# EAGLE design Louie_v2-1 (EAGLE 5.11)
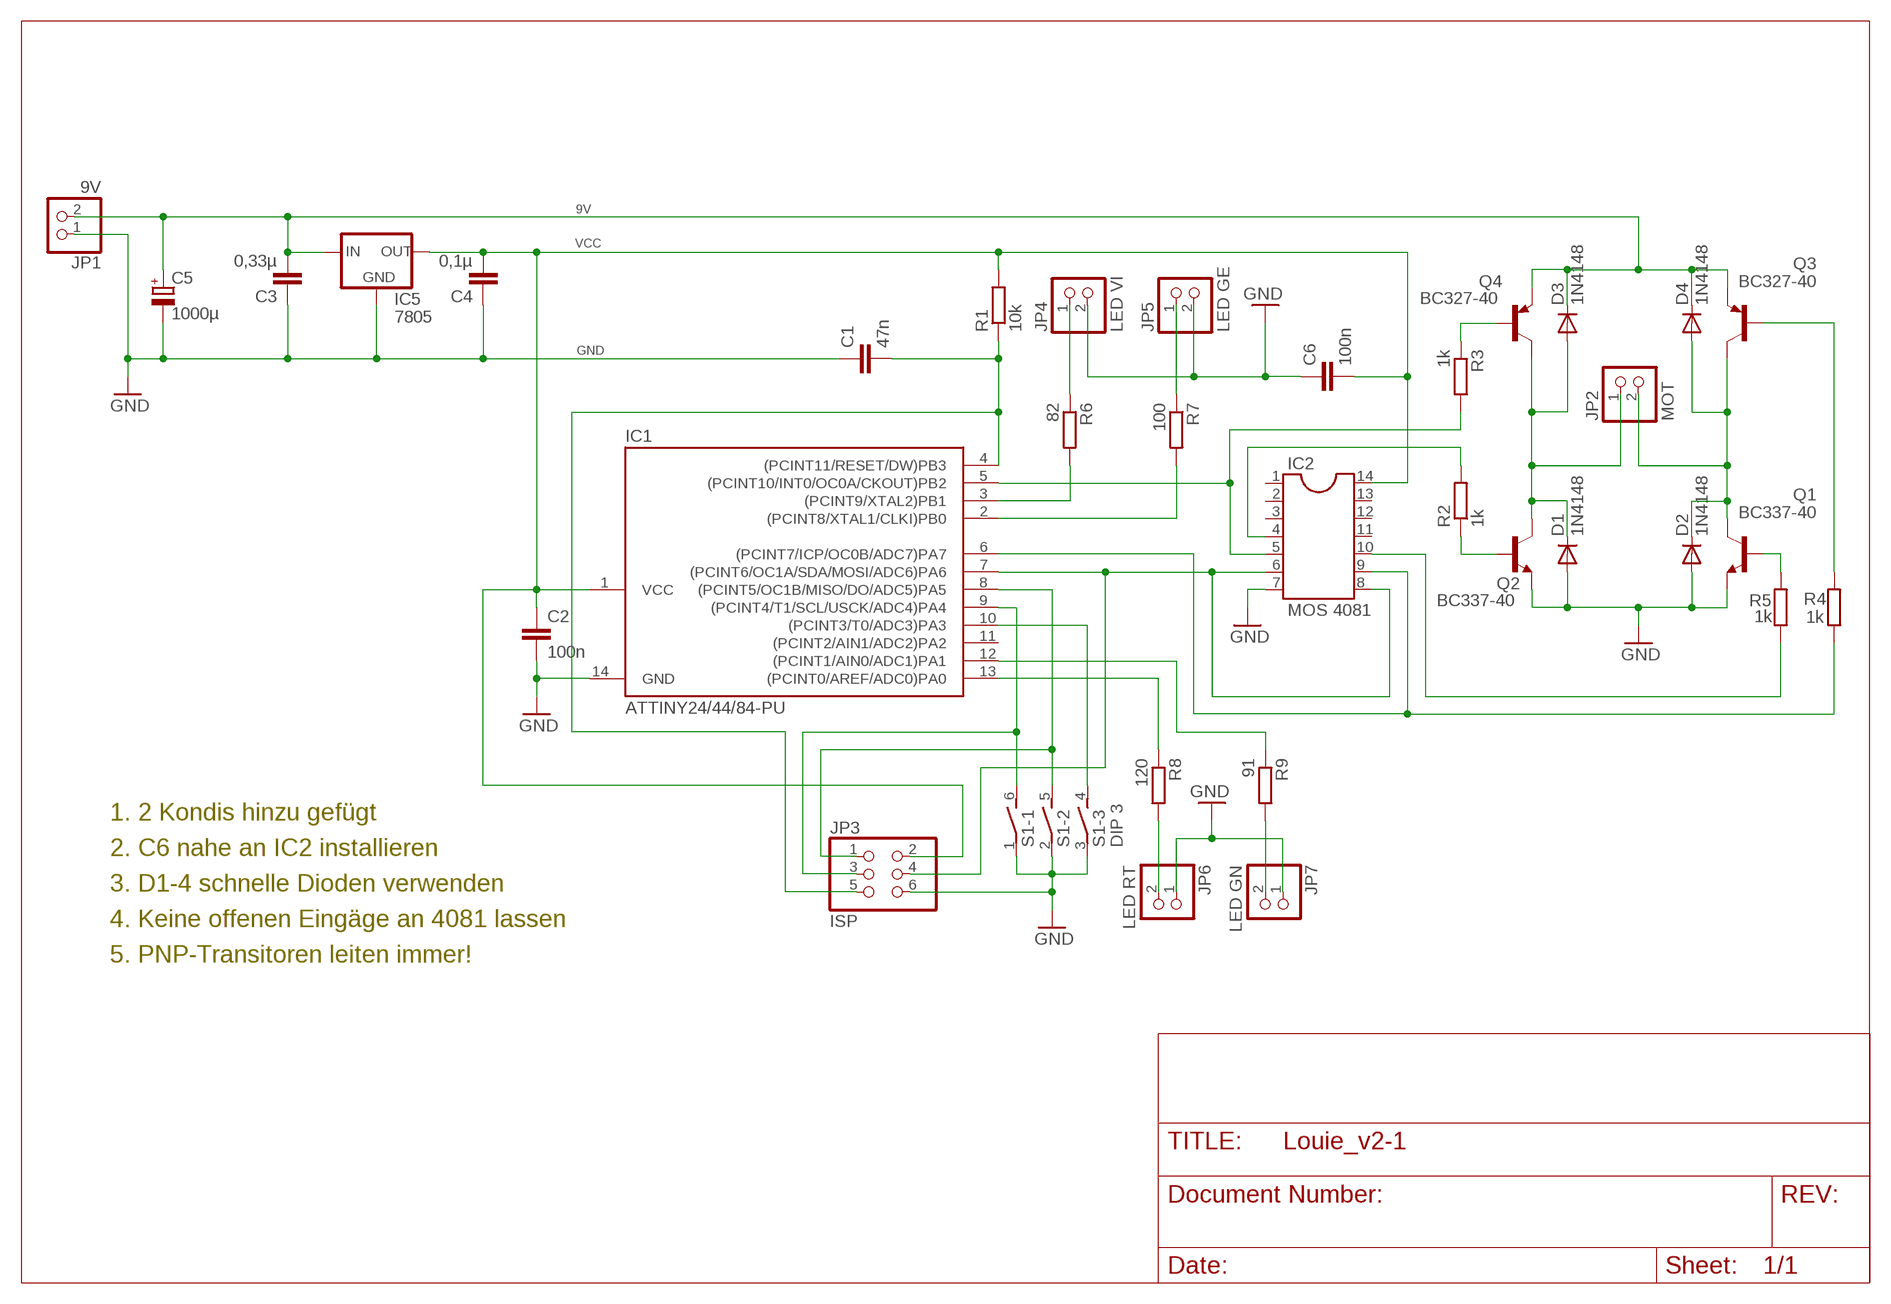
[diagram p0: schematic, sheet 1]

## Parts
C1  47n  C-EU025-025X050  [C025-025X050]
C2  100n  C-EU050-024X044  [C050-024X044]
C3  0,33µ  C-EU025-025X050  [C025-025X050]
C4  0,1µ  C-EU025-025X050  [C025-025X050]
C5  1000µ  CPOL-EUE5-10.5  [E5-10,5]
C6  100n  C-EU050-024X044  [C050-024X044]
D1  1N4148  [DO35-10]
D2  1N4148  [DO35-10]
D3  1N4148  [DO35-10]
D4  1N4148  [DO35-10]
IC1  ATTINY24/44/84-PU  [DIL14]
IC2  MOS 4081  DIL14  [DIL14]
IC5  7805  78XXL  [78XXL]
JP1  9V  PINHD-1X2  [1X02]
JP2  MOT  PINHD-1X2  [1X02]
JP3  ISP  PINHD-2X3  [2X03]
JP4  LED VI  PINHD-1X2  [1X02]
JP5  LED GE  PINHD-1X2  [1X02]
JP6  LED RT  PINHD-1X2  [1X02]
JP7  LED GN  PINHD-1X2  [1X02]
Q1  BC337-40  BC337  [TO92]
Q2  BC337-40  BC337  [TO92]
Q3  BC327-40  BC327  [TO92-EBC]
Q4  BC327-40  BC327  [TO92-EBC]
R1  10k  R-EU_0309/V  [0309V]
R2  1k  R-EU_0309/V  [0309V]
R3  1k  R-EU_0309/V  [0309V]
R4  1k  R-EU_0309/V  [0309V]
R5  1k  R-EU_0309/V  [0309V]
R6  82  R-EU_0309/V  [0309V]
R7  100  R-EU_0309/V  [0309V]
R8  120  R-EU_0309/V  [0309V]
R9  91  R-EU_0309/V  [0309V]
S1  DIP 3  DS03E  [DS-03]

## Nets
9V: C3.2 C5.+ D3.C D4.C IC5.IN JP1.2 Q3.E Q4.E
GND: C1.1 C2.2 C3.1 C4.1 C5.- C6.1 D1.A D2.A IC1.14(GND) IC2.7 IC5.GND JP1.1 JP3.6 JP4.2 JP5.2 JP6.1 JP7.1 Q1.1(E) Q2.1(E) S1.1 S1.2 S1.3
N$1: IC1.7((PCINT6/OC1A/SDA/MOSI/ADC6)PA6) IC2.6 IC2.8 JP3.4
N$2: IC1.6((PCINT7/ICP/OC0B/ADC7)PA7) IC2.9 R4.1
N$3: IC1.5((PCINT10/INT0/OC0A/CKOUT)PB2) IC2.5 R3.2
N$4: D1.C D3.A JP2.1 Q2.3(C) Q4.C
N$7: C1.2 IC1.4((PCINT11/RESET/DW)PB3) JP3.5 R1.1
N$8: D2.C D4.A JP2.2 Q1.3(C) Q3.C
N$9: Q2.2(B) R2.1
N$10: Q4.B R3.1
N$11: Q3.B R4.2
N$12: Q1.2(B) R5.2
N$13: IC1.8((PCINT5/OC1B/MISO/DO/ADC5)PA5) JP3.1 S1.5
N$14: IC2.4 R2.2
N$15: IC2.10 R5.1
N$16: IC1.9((PCINT4/T1/SCL/USCK/ADC4)PA4) JP3.3 S1.6
N$17: IC1.3((PCINT9/XTAL2)PB1) R6.2
N$18: IC1.10((PCINT3/T0/ADC3)PA3) S1.4
N$19: IC1.2((PCINT8/XTAL1/CLKI)PB0) R7.2
N$20: JP4.1 R6.1
N$21: JP5.1 R7.1
N$22: IC1.12((PCINT1/AIN0/ADC1)PA1) R9.1
N$23: JP7.2 R9.2
N$24: IC1.13((PCINT0/AREF/ADC0)PA0) R8.1
N$26: JP6.2 R8.2
VCC: C2.1 C4.2 C6.2 IC1.1(VCC) IC2.14 IC5.OUT JP3.2 R1.2
Unconnected: IC1.11((PCINT2/AIN1/ADC2)PA2) IC2.1 IC2.2 IC2.3 IC2.11 IC2.12 IC2.13

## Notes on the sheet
- 1. 2 Kondis hinzu gefügt
- 2. C6 nahe an IC2 installieren
- 3. D1-4 schnelle Dioden verwenden
- 4. Keine offenen Eingäge an 4081 lassen
- 5. PNP-Transitoren leiten immer!

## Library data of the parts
C1-C4 C6 = rcl:C-EU: CAPACITOR, European symbol
C5 = rcl:CPOL-EU: POLARIZED CAPACITOR, European symbol
D1-D4 = diode:1N4148: DIODE
IC1 = attiny24_44_84:ATTINY24/44/84
IC2 = ic-package:DIL14: Dual In Line / Socket
IC5 = v-reg:78XXL: VOLTAGE REGULATOR
JP1 JP2 JP4-JP7 = pinhead:PINHD-1X2: PIN HEADER
JP3 = pinhead:PINHD-2X3: PIN HEADER
Q1 Q2 = transistor-npn:BC337*: NPN Transistor
Q3 Q4 = transistor-pnp:BC327*: PNP Transistror
R1-R9 = rcl:R-EU_: RESISTOR, European symbol
S1 = switch-dil:DS03E: DIL/CODE SWITCH

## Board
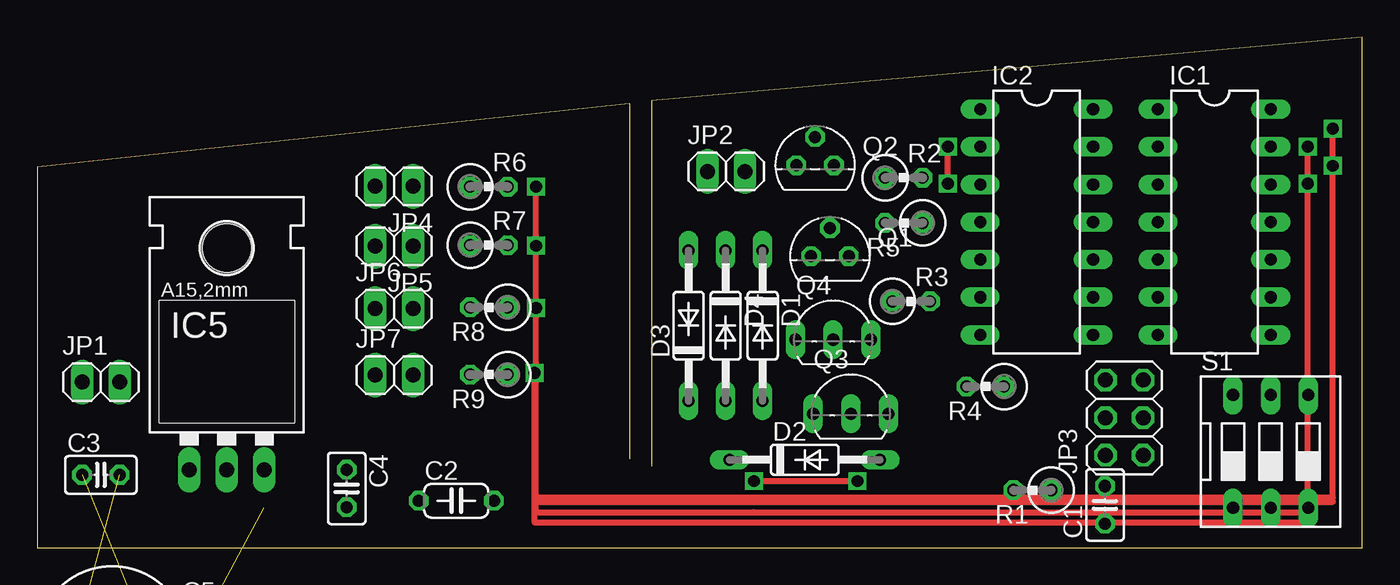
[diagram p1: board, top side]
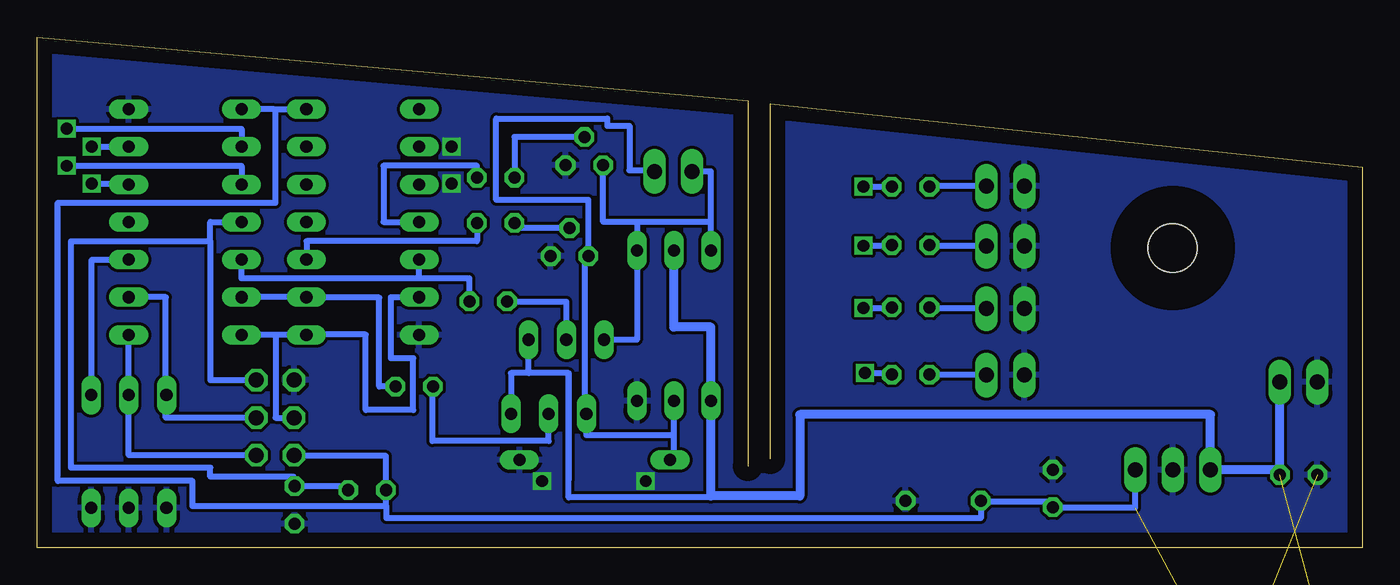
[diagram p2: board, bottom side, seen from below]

Size 89.5 x 34.5 mm. Coordinates in mm from the lower left corner, seen from the top.
Outline: 41.5,5.5 41.5,30.2 89.5,34.5 89.5,0 0,0 0,25.7 40,30 40,6
Copper layers (1*16): Top 0.035mm / dielectric 1.5mm / Bottom 0.035mm
Design rules "default": minimum track width 10mil, minimum drill 24mil, track to track 8mil, track to pad 8mil, pad to pad 8mil, via to via 8mil, smd to smd 8mil, copper to edge 40mil, drill to drill 8mil, minimum pad ring 10mil, minimum via ring 8mil, stop-mask expansion 4mil, vias tented up to drill 0mil, thermal gap 10mil

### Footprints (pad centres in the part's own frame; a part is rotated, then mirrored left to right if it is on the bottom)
C025-025X050 = drill 0.813 octagon: 1 -1.27,0; 2 1.27,0
C050-024X044 = drill 0.813 octagon: 1 -2.54,0; 2 2.54,0
E5-10,5 = drill 1.016 pad 2.54 round: + -2.54,0 | drill 1.016 pad 2.54 octagon: - 2.54,0
DO35-10 = drill 0.813 long: A 5.08,0; C -5.08,0
DIL14 = drill 0.813 long: 1 -7.62,-3.81; 2 -5.08,-3.81; 3 -2.54,-3.81; 4 0,-3.81; 5 2.54,-3.81; 6 5.08,-3.81; 7 7.62,-3.81; 8 7.62,3.81; 9 5.08,3.81; 10 2.54,3.81; 11 0,3.81; 12 -2.54,3.81; 13 -5.08,3.81; 14 -7.62,3.81
78XXL = drill 1.016 long: GND 0,-3.81; IN -2.54,-3.81; OUT 2.54,-3.81 | hole 3.302: 0,11.176
1X02 = drill 1.016 long: 1 -1.27,0; 2 1.27,0
2X03 = drill 1.016 octagon: 1 -2.54,-1.27; 2 -2.54,1.27; 3 0,-1.27; 4 0,1.27; 5 2.54,-1.27; 6 2.54,1.27
TO92 = drill 0.813 octagon: 1 1.27,0; 2 0,1.905; 3 -1.27,0
TO92-EBC = drill 0.813 long: B 0,-1.27; C -2.54,-1.27; E 2.54,-1.27
0309V = drill 0.813 octagon: 1 -1.27,0; 2 1.27,0
DS-03 = drill 0.813 long: 1 -2.54,-3.81; 2 0,-3.81; 3 2.54,-3.81; 4 2.54,3.81; 5 0,3.81; 6 -2.54,3.81

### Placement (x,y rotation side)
C1  72.11,2.89 90 top
C2  28.31,3.17 0 top
C3  4.31,4.92 0 top
C4  20.91,4 270 top
C5  not placed on the board
C6  not placed on the board
D1  49,15 270 top
D2  51.84,5.94 0 top
D3  44,15 90 top
D4  46.5,15 270 top
IC1  79.5,22 270 top
IC2  67.5,22 270 top
IC5  12.81,9.07 0 top
JP1  4.31,11.19 0 top
JP2  46.53,25.42 0 top
JP3  73.42,8.78 90 top
JP4  24.11,24.42 180 top
JP5  24.11,20.37 180 top
JP6  24.11,16.15 0 top
JP7  24.11,11.66 0 top
Q1  53.54,19.69 0 top
Q2  52.54,25.84 0 top
Q3  54.95,10.32 0 top
Q4  53.76,15.32 0 top
R1  67.21,3.89 180 top
R2  58.53,24.99 0 top
R3  59.03,16.64 0 top
R4  64.03,10.89 180 top
R5  58.53,21.94 180 top
R6  30.51,24.39 0 top
R7  30.51,20.44 0 top
R8  30.51,16.24 180 top
R9  30.51,11.69 180 top
S1  83.3,6.5 0 top

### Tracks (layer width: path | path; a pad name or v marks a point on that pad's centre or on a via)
9V  (1 unrouted)
  Bottom 0.406: 56.3,11.8 Q4.E | 53.6,11.8 56.3,11.8 | 53.6,11.8 53.6,4.6 | Q3.E 57.5,9 | Q3.E | 56.3,11.8 57.5,11.8 Q3.E | 44,3.5 44,3.4 53.6,3.4 53.6,11.8
  Bottom 0.61: JP1.2 C3.2 5.58,5.26 IC5.IN 10.27,9 38,9 38,3.5 44,3.5 D3.C 44,14.9 46.5,14.9 D4.C
GND  (via drill 0.8)  (2 unrouted)
  Top 0.406: v61.5,24.6 v61.5,27.1 | v48.4,4.5 v55.4,4.5
  pour Bottom: 0,0 89.25,0 arc90 89.5,0.25 89.5,35 0.25,35 arc90 0,34.75
N$1
  Bottom 0.406: 73.4,14.38 IC2.8 71.31,14.4 67.3,14.4 67.3,9.3 64.1,9.3 64.1,12.8 65.6,12.8 65.6,16.92 IC2.6 | 73.4,14.38 IC1.7 | JP3.4 73.4,8.78 73.4,14.38
N$2
  Bottom 0.406: IC1.6 IC2.9 71.31,16.9 | R4.1 66.4,10.89 66.4,16.9 71.31,16.9 | 71.31,16.9 71.4,16.9
N$3
  Bottom 0.406: 63.69,18.2 IC2.5 | 63.69,18.2 60.3,18.2 R3.2 | 63.69,18.2 75.69,18.2 IC1.5
N$4
  Bottom 0.406: JP2.1 44,25.42 44,22 | D3.A 44,22 | 44,22 49,22 | 49,22 D1.C 49,14.05 Q4.C | 49,22 51.27,22 Q2.3
N$7
  Bottom 0.406: 77.8,20.7 77.8,11.32 JP3.5 | 77.8,20.7 77.8,22 IC1.4 | 77.8,20.7 87.2,20.7 87.2,5.4 77.8,5.4 77.8,4.8 72.2,4.8 72.2,4.16 C1.2 68.5,4.16 68.5,3.89 | 68.5,3.89 68.5,3.8 | R1.1 68.5,3.89
N$8
  Bottom 0.406: JP2.2 47.8,25.5 49.5,25.5 49.5,28.5 51,28.5 51,29 58.5,29 58.5,23.5 52.27,23.5 Q1.3 52.5,19.69 52.5,9.05 Q3.C 52.41,7.6 46.5,7.6 | 46.76,5.9 46.8,5.9 | D2.C 46.76,5.9 | 46.5,7.6 46.5,5.9 46.76,5.9 | 46.5,7.6 D4.A
N$9
  Bottom 0.406: R2.1 57.26,27.75 Q2.2
N$10
  Bottom 0.406: 57.76,16.6 57.8,16.6 | 57.76,16.6 R3.1 | Q4.B 53.76,16.6 57.76,16.6
N$11
  Bottom 0.406: Q3.B 54.95,7.2 62.8,7.2 62.8,10.9 R4.2
N$12
  Bottom 0.406: Q1.2 57.26,21.59 R5.2
N$13
  Bottom 0.406: IC1.8 83.3,10.5 | 83.3,10.5 S1.5 | JP3.1 83.3,6.24 83.3,10.5
N$14
  Bottom 0.406: R2.2 59.8,25.8 66.1,25.8 66.1,22 IC2.4
N$15
  Bottom 0.406: R5.1 59.8,20.7 71.31,20.7 IC2.10
N$16
  Bottom 0.406: JP3.3 80.8,8.78 80.8,10.3 | 80.8,10.3 80.8,10.31 S1.6 | IC1.9 80.8,16.92 80.8,10.3
N$17  (via drill 0.8)
  Top 0.406: v87.5,25.8 87.5,3.4 33.7,3.4 v33.7,24.39
  Bottom 0.406: v33.7,24.39 R6.2 | IC1.3 75.69,25.8 v87.5,25.8
N$18
  Bottom 0.406: 85.8,10.31 85.8,10.3 | S1.4 85.8,10.31 | IC1.10 85.8,19.46 85.8,10.31
N$19  (via drill 0.8)
  Top 0.406: v87.5,28.3 87.5,3.1 33.7,3.1 v33.7,20.4
  Bottom 0.406: IC1.2 75.69,28.3 v87.5,28.3 | R7.2 31.78,20.4 v33.7,20.4
N$20
  Bottom 0.406: R6.1 29.3,24.39 29.3,24.42 JP4.1
N$21
  Bottom 0.406: R7.1 29.2,20.44 29.2,20.37 JP5.1
N$22  (via drill 0.8)
  Top 0.406: v85.8,24.6 85.8,1.7 33.6,1.7 v33.6,11.8
  Bottom 0.406: IC1.12 83.31,24.6 v85.8,24.6 | R9.1 31.78,11.8 v33.6,11.8
N$23
  Bottom 0.406: 29.2,11.66 29.2,11.69 R9.2 | JP7.2 29.2,11.66 | 29.2,11.66 29.2,11.6
N$24  (via drill 0.8)
  Top 0.406: v85.8,27.1 85.8,2.4 48.4,2.4 33.7,2.4 v33.7,16.2
  Bottom 0.406: IC1.13 83.31,27.1 v85.8,27.1 | R8.1 31.78,16.2 v33.7,16.2
N$26
  Bottom 0.406: R8.2 29.2,16.24 29.2,16.15 JP6.2
VCC  (1 unrouted)
  Bottom 0.406: IC2.14 | 73.5,29.62 IC2.14 | 73.5,29.62 IC1.1 | IC2.14 71.3,29.6 | 73.5,29.62 73.5,29.6 73.4,29.6 73.4,23.3 88.1,23.3 88.1,4.5 79,4.5 79,2.8 66.1,2.8 | 72.15,6.2 72.2,6.2 | 72.15,6.2 JP3.2 | 72.15,6.2 65.94,6.2 R1.2 65.94,2.8 66.1,2.8 | IC5.OUT 15.35,2.7 20.9,2.7 | 20.9,2.7 21,2.7 | 66.1,2.8 65.9,2.8 65.9,2 25.77,2 C2.1 25.77,3.1 20.91,3.1 C4.2 20.91,2.8 20.9,2.8 20.9,2.7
